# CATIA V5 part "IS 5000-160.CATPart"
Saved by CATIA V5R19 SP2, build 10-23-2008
Part number: IS 5000-160
Bounding box of the stored display mesh (mm): x -59.975 to 59.975, y -59.975 to 59.975, z 0 to 460
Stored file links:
  C:\Users\Bora\Desktop\3D Katı model\IS serisi\IS 5000\IS 5000-160.CATPart
  C:\Program Files\Dassault Systemes\B19\intel_a\reffiles\standard\MetricThickPitch.txt
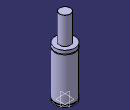
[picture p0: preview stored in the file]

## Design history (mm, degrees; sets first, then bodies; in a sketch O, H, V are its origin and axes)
Body1 (main body)
  Sketch1 on yz-plane, origin (0, 0, 0), H (0, 1, 0), V (0, 0, 1)
    point P1 (60, 277)
    point P2 (60, 272)
    point P5 (32.5, 459)
    point P7 (32.5, 459)
    point P12 (60, 272)
    point P13 (60, 277)
    arc A1 centre (60, 274.5) radius 2.5 from (60, 277) to (60, 272) ccw
    line L1 (60, 0) -> (60, 8)
    line L2 (32.5, 459) -> (32.5, 297)
    arc A2 centre (31.5, 459) radius 1 from (32.5, 459) to (31.5, 460) ccw
    line L3 (56, 13) -> (56, 8)
    line L4 (60, 13) -> (60, 272)
    line L5 (60, 277) -> (60, 297)
    line L6 (31.5, 460) -> (0, 460)
    point P15 (0, 460)
    line L7 (32.5, 297) -> (60, 297)
    line L8 (0, 0) -> (60, 0)
    line L9 (56, 13) -> (60, 13)
    line L10 (56, 8) -> (60, 8)
    coincidence: P15 V, P1 P13, P2 P12, P5 P7
    tangency: L6 A2
    horizontal: L7 H, L8 H, L9 H, L10 H
  Shaft1: profile Sketch1, axis Sketch1.V, angle 360
  Sketch2 on face of Shaft1 from Sketch1.L8, origin (0, 0, 0), H (1, 0, 0), V (0, -1, 0)
    point P1 (40, 0)
    distance P1 V = 40
  Hole1: placed by Sketch2, at (40, 0, 0) direction (0, 0, 1), diameter 8.376, depth 16, threaded "M10", thread diameter 10, thread depth 16, pitch 1.5
  CircPattern1: of Hole1, instances 4, angular step 90, axis from face of Shaft1 from Sketch1.L8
